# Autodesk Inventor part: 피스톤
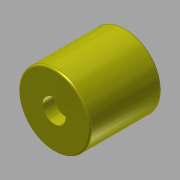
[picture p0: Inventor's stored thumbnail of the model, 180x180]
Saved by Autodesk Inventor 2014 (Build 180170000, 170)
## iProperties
Created: 2018-01
Part Number: 피스톤
Material: 강철, 탄소
Document SubType Name: Modeling
Designer: mduedu
Density: 1 g/cm^3
Appearance: 노란색
Author: mduedu
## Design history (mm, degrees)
sketch "스케치1"
  geometry: C1 r 10 at (0, 0); 1 further point
  constraints: 1 centre point, 1 coincident
  dimensions: "d0" = 20 diameter of C1
extrude "돌출1" new body sketch "스케치1" distance "d1" = 20; taper "d2" = 0 deg
hole "구멍1" diameter "d5" = 7; stored, may be unused: countersink angle "d9" = 90 deg, drill point angle "d11" = 0 deg; dims "d6" = 6, "d7" = 4, "d8" = 2, "d10" = 10, "d12" = 10, "d13" = 10
chamfer "모따기1" distance "d14" = 0.5; stored, may be unused: second distance "d15" = 2, angle "d16" = 45 deg
fillet "모깎기1" dims "d17" = 0.5
sketch "스케치2"
  geometry: 2 further points
  constraints: 1 coincident
sketch "스케치3"
  geometry: 2 further points
  constraints: 1 coincident
hole "구멍2" sketch "스케치3" at (0, 0) diameter "d18" = 3.4; stored, may be unused: countersink angle "d22" = 90 deg, drill point angle "d24" = 0 deg; dims "d19" = 6, "d20" = 6.5, "d21" = 3.4, "d23" = 8
node "솔리드1"
